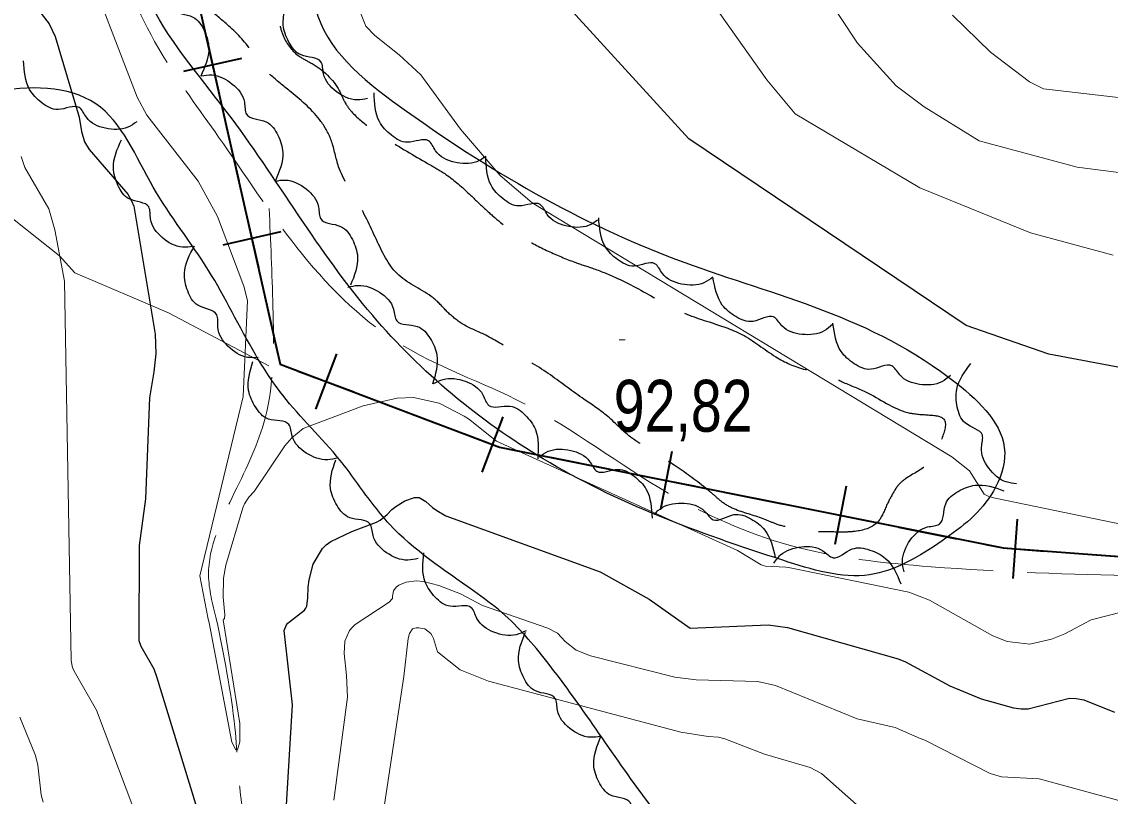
# Model space of a CAD drawing. Extents: x 483843 to 488449, y 4381269 to 4384483.
# Drawn here: x 486032.4 to 486216, y 4382919.1 to 4383049.8 of the extents above; entities that cross this region are included whole.
import ezdxf

# ---------------------------------------------------------------- set-up
doc = ezdxf.new("R2010")
doc.units = 0
doc.header["$LTSCALE"] = 3.8
doc.linetypes.add('LONG_DASHED', pattern=[7.5, 6, -1.5])
for name, color, linetype, lineweight in [('15', 7, 'LONG_DASHED', 13), ('25', 7, 'LONG_DASHED', 25), ('27', 7, 'Continuous', 25), ('34', 7, 'Continuous', 35), ('51', 7, 'Continuous', 13), ('7', 7, 'Continuous', 13), ('8', 7, 'Continuous', 25), ('9', 7, 'Continuous', 13)]:
    doc.layers.add(name, color=color, linetype=linetype, lineweight=lineweight)

msp = doc.modelspace()

# ---------------------------------------------------------------- linework, layer by layer
at = {"layer": '15'}
for points in [[(485400.79, 4383245.56), (485406.29, 4383244.41), (485437.45, 4383238.77), (485468.96, 4383231.4), (485504.33, 4383230.87), (485548.91, 4383220.24), (485591.04, 4383211.58), (485622.86, 4383204.36), (485651.32, 4383198.17), (485680.8, 4383195.25), (485706.08, 4383191.57), (485722.37, 4383193.95), (485735.23, 4383201.55), (485745.53, 4383213.76), (485759.02, 4383234.02), (485775.19, 4383262.78), (485795.18, 4383296.65), (485816.27, 4383323.61), (485841.16, 4383349.54), (485867.84, 4383369.45), (485913.47, 4383388.85), (485935.22, 4383394.97), (485958.89, 4383388.99), (485973.47, 4383381.81), (485979.32, 4383377.07), (485984.47, 4383370.85), (485987.04, 4383362.27), (485987.36, 4383354.02), (485987.36, 4383343.75), (485982.84, 4383337.15), (485969.6, 4383328.73), (485958.55, 4383321.85), (485945.63, 4383309.53), (485931.32, 4383300.15), (485906.76, 4383286.36), (485891.85, 4383276.39), (485880.57, 4383264.12), (485871.36, 4383244.47), (485865.12, 4383222.84), (485860.75, 4383191.43), (485865.12, 4383163.11), (485877.56, 4383143.14), (485893.96, 4383132.18), (485911.26, 4383131.69), (485923.31, 4383135.71), (485933.99, 4383143.04), (485949.29, 4383153.83), (485962.9, 4383167.19), (485985.6, 4383171.87), (486005.81, 4383170.22), (486029.34, 4383160.05), (486043.95, 4383149.41), (486042.89, 4383138.86), (486041.88, 4383131.75), (486041.4, 4383119.4), (486046.63, 4383078.7), (486048.42, 4383062.79), (486056.08, 4383044.24), (486065.61, 4383030.31), (486078.82, 4383011.67), (486095.82, 4382995.68), (486117.1, 4382985.39), (486141.45, 4382970.26), (486161.85, 4382961.49), (486185.85, 4382957.83), (486221.05, 4382956.33), (486256.43, 4382956.62), (486292.45, 4382960.13), (486324.15, 4382965.13)], [(486074.14, 4383018.28), (486074.78, 4383001.69), (486073.45, 4382982.9), (486068.31, 4382970.39), (486063.91, 4382956.44), (486065.22, 4382949.08)], [(486065.22, 4382949.08), (486068.35, 4382930.7), (486069.57, 4382917.3), (486071.08, 4382908.17), (486071.58, 4382901.05), (486070.87, 4382894.66), (486068.25, 4382890.26), (486062.57, 4382880.56), (486059.04, 4382876.29), (486052.85, 4382870.03), (486046.08, 4382862.7), (486043.37, 4382858.83), (486038.17, 4382851.61), (486033.87, 4382844.85), (486028.35, 4382834.48), (486026.38, 4382826.86), (486024.21, 4382822.55), (486017.26, 4382812.6), (486008.1, 4382800.28), (485993.48, 4382782.38), (485975.18, 4382760.9), (485963.64, 4382747.64), (485957.75, 4382737.18), (485954.51, 4382729.62), (485952.12, 4382724.77), (485950.95, 4382722.8), (485947.3, 4382716.88), (485942.92, 4382710.35), (485938.93, 4382702.4), (485932.72, 4382688.86), (485930.2, 4382678.69), (485929.47, 4382673.2), (485929.22, 4382666.52), (485929.23, 4382661.56), (485945.62, 4382617.44), (485946.62, 4382612.05), (485946.07, 4382605.06), (485939.39, 4382592.57), (485935.24, 4382580.86), (485934.32, 4382573.72), (485932.79, 4382562.81), (485931.33, 4382552.28), (485929.61, 4382543.47), (485925.71, 4382534.7), (485922.35, 4382529.61), (485920.15, 4382522.44), (485919, 4382506.82), (485919.09, 4382501.71), (485919.55, 4382484.39), (485919.25, 4382472.08), (485919.24, 4382464.2), (485918.57, 4382446.78), (485919.45, 4382426.99), (485920.81, 4382413.51), (485921.23, 4382407.06), (485920.41, 4382402.4), (485918.93, 4382396.89), (485917.32, 4382390.64), (485916.53, 4382388.45), (485911.11, 4382376.87), (485903.16, 4382363.9), (485897.69, 4382359.6), (485889.85, 4382348.8), (485888.47, 4382342.25), (485885.05, 4382333.08)]]:
    msp.add_spline(points, degree=3, dxfattribs=at)
at = {"layer": '25'}
for points in [[(486047.77, 4383119.06), (486047.87, 4383123.7), (486050.32, 4383126.96), (486057.32, 4383128.74), (486055.98, 4383129.28), (486056.91, 4383131.52), (486059.09, 4383131.79), (486063.4, 4383123.4), (486063.36, 4383120.85), (486067.05, 4383111.49), (486070.05, 4383106.12), (486072.24, 4383101.66), (486074.34, 4383096.76), (486075.26, 4383092.47), (486076.22, 4383085.92), (486076.34, 4383084.05), (486076.23, 4383081.87), (486076.15, 4383076.02), (486076.05, 4383074.14), (486075.99, 4383070.32), (486075.86, 4383066.04), (486075.99, 4383065.14), (486076.95, 4383064), (486078.58, 4383062.48), (486078.87, 4383061.87), (486077.97, 4383061.74), (486077.14, 4383061.75), (486076.99, 4383061.68), (486076.46, 4383061.31), (486075.61, 4383059.22), (486075.27, 4383056.67), (486075.13, 4383052.1), (486075.77, 4383049.69), (486076.56, 4383047.27), (486079.22, 4383043.93), (486081.37, 4383042.7), (486085.96, 4383038.14), (486087.05, 4383035.94), (486087.86, 4383034.81), (486090.98, 4383031.99), (486094.32, 4383029.76), (486101.31, 4383025.61), (486104.29, 4383023.77), (486108.14, 4383020.48), (486110.81, 4383017.97), (486113.18, 4383015.91), (486116.82, 4383013.38), (486121.22, 4383011.07), (486125.69, 4383009.2), (486128.9, 4383008.11), (486132.93, 4383006.47), (486139.86, 4383002.77), (486141.79, 4383001.69), (486148.36, 4382999.12), (486153.88, 4382997.02), (486159.6, 4382993.26), (486164.6, 4382991.09), (486168.12, 4382990.29), (486170.8, 4382989.05), (486174.75, 4382987.34), (486181.83, 4382983.86), (486185.35, 4382983.44), (486187.97, 4382982.72), (486187.62, 4382979.43), (486185.16, 4382975.03), (486181.52, 4382972.69), (486180.15, 4382971.43), (486179.61, 4382970.61), (486178.3, 4382968.15), (486176.69, 4382965.25), (486172.99, 4382963.8), (486171.04, 4382963.68), (486167.29, 4382963.74), (486165.78, 4382963.76), (486162.57, 4382964.33), (486159.87, 4382964.97), (486157.79, 4382965.82), (486152.86, 4382967.47), (486150.62, 4382968.7), (486149.36, 4382969.77), (486147.73, 4382971.14), (486142.46, 4382974.97), (486138, 4382977.81), (486135.1, 4382979.73), (486131.02, 4382983.39), (486126.94, 4382986.3), (486121.22, 4382990.43), (486115.12, 4382994.27), (486110.36, 4382997.04), (486106.71, 4382998.82), (486104.11, 4383000.88)], [(486104.11, 4383000.88), (486101.82, 4383003.17), (486096.02, 4383007), (486092.42, 4383012.61), (486089.07, 4383019.33), (486085.85, 4383025.31), (486084.64, 4383029.68), (486082.88, 4383032.93), (486077.85, 4383037.88), (486074.52, 4383040.63), (486072.52, 4383042.61), (486071.12, 4383044.8), (486067.06, 4383049.29), (486064.02, 4383051.88), (486062.17, 4383053.56), (486060.09, 4383055.09), (486057.86, 4383056.47), (486057.5, 4383057.53), (486056.29, 4383062.05), (486055.07, 4383076.17), (486053.75, 4383083.54), (486049.3, 4383087.21), (486048.84, 4383092.32), (486048.95, 4383099.6), (486048.96, 4383105.97), (486048.61, 4383112.96), (486045.38, 4383117.3)]]:
    msp.add_spline(points, degree=3, dxfattribs=at)
at = {"layer": '27'}
for points in [[(486069.89, 4383117.75), (486082.64, 4383091.41), (486082.37, 4383068.06), (486082.37, 4383050.69), (486097.3, 4383034.67), (486144.24, 4383009.15), (486190.1, 4382988.79), (486198.24, 4382977.12), (486196.34, 4382970.6), (486187.66, 4382962.19), (486175.45, 4382956.48), (486160.79, 4382958.93), (486120.36, 4382976.03), (486091.6, 4383000.19), (486066.9, 4383034.67), (486053.61, 4383053.95), (486049.81, 4383066.98), (486048.18, 4383082.45), (486040.85, 4383115.3), (486038.68, 4383122.9), (486038.68, 4383126.16), (486042.21, 4383132.14), (486051.17, 4383136.21), (486059.31, 4383137.29), (486063.38, 4383135.12), (486064.73, 4383132.95), (486069.89, 4383118.02)], [(486050.49, 4383058.59), (486052.26, 4383058.7), (486055.69, 4383057.07), (486057.66, 4383053.95), (486057.98, 4383051.92), (486061.26, 4383050.56), (486063.17, 4383048.27), (486063.95, 4383045.35), (486062.59, 4383040.57)], [(486090.74, 4383036.79), (486088.98, 4383036.58), (486085.46, 4383038), (486083.31, 4383041), (486082.87, 4383043), (486079.51, 4383044.16), (486077.47, 4383046.34), (486076.51, 4383049.21), (486077.59, 4383054.05)], [(486051.8, 4383032.89), (486050.29, 4383031.97), (486046.5, 4383031.8), (486043.3, 4383033.65), (486042.07, 4383035.29), (486038.53, 4383034.96), (486035.77, 4383036.1), (486033.72, 4383038.32), (486032.69, 4383043.17)], [(486062.68, 4383040.65), (486064.44, 4383040.79), (486067.91, 4383039.25), (486069.95, 4383036.18), (486070.31, 4383034.15), (486073.63, 4383032.87), (486075.59, 4383030.62), (486076.44, 4383027.72), (486075.19, 4383022.92)], [(486286.37, 4382818.73), (486278.04, 4382823.01), (486270.91, 4382827.39), (486261.25, 4382830.52), (486249.55, 4382838.56), (486235.78, 4382853.4), (486208.71, 4382873.4), (486199.54, 4382878.26), (486190.05, 4382880.8), (486172.3, 4382887.23), (486138.6, 4382917.4), (486120.98, 4382941.85), (486113.4, 4382950.11), (486108.61, 4382953.78), (486094.45, 4382965.01), (486088.77, 4382972.26), (486086.08, 4382975.81), (486076.44, 4382986.75), (486071.81, 4382993.64), (486063.9, 4383007.83), (486054.58, 4383021.85), (486044.87, 4383035.93), (486027.43, 4383037.8), (485933.61, 4382938.44), (485919.77, 4382940.14), (485889.7, 4382939.08), (485839.54, 4382941.26), (485816.75, 4382944.76), (485741.23, 4382929.61), (485713.92, 4382937.9), (485681.19, 4382964.56), (485670.78, 4382975.78), (485652.13, 4382986.85), (485638.34, 4382985.71), (485603.43, 4382978.48), (485583.93, 4382969.73), (485574.59, 4382959.14), (485576.9, 4382938.62), (485580.71, 4382884.66), (485577.11, 4382863.44), (485511.92, 4382842.02), (485496.71, 4382848.88), (485482.18, 4382864.38), (485474.15, 4382877.06), (485456.13, 4382915.83), (485453.46, 4382926.82), (485449.3, 4382945.73), (485443.9, 4382957.94), (485427.92, 4382978.81), (485418.61, 4382987.72), (485404.26, 4383001.65), (485381.54, 4383009.27), (485374.73, 4383011.94)], [(486110.69, 4383027.03), (486109.15, 4383026.15), (486105.36, 4383026.08), (486102.21, 4383028), (486101.02, 4383029.68), (486097.48, 4383029.43), (486094.75, 4383030.65), (486092.75, 4383032.91), (486091.85, 4383037.79)], [(486061.29, 4383011.84), (486059.52, 4383011.73), (486056.09, 4383013.36), (486054.13, 4383016.49), (486053.82, 4383018.52), (486050.53, 4383019.88), (486048.63, 4383022.18), (486047.85, 4383025.1), (486049.22, 4383029.87)], [(486129.53, 4383016.28), (486127.99, 4383015.4), (486124.2, 4383015.33), (486121.05, 4383017.26), (486119.86, 4383018.93), (486116.32, 4383018.69), (486113.59, 4383019.9), (486111.59, 4383022.17), (486110.69, 4383027.05)], [(486075.13, 4383022.88), (486076.89, 4383023.06), (486080.38, 4383021.56), (486082.46, 4383018.51), (486082.85, 4383016.49), (486086.18, 4383015.25), (486088.17, 4383013.02), (486089.05, 4383010.13), (486087.87, 4383005.32)], [(486149, 4383006.69), (486147.5, 4383005.74), (486143.71, 4383005.52), (486140.48, 4383007.31), (486139.23, 4383008.94), (486135.7, 4383008.55), (486132.92, 4383009.65), (486130.83, 4383011.83), (486129.73, 4383016.67)], [(486072.26, 4382993.12), (486070.49, 4382993.15), (486067.19, 4382995.02), (486065.46, 4382998.28), (486065.3, 4383000.33), (486062.12, 4383001.93), (486060.39, 4383004.36), (486059.83, 4383007.34), (486061.55, 4383011.99)], [(486169.19, 4382998.72), (486167.79, 4382997.63), (486164.05, 4382997.02), (486160.65, 4382998.47), (486159.24, 4382999.96), (486155.77, 4382999.21), (486152.89, 4383000.02), (486150.59, 4383001.98), (486149, 4383006.67)], [(486087.42, 4383004.97), (486089.16, 4383005.3), (486092.77, 4383004.13), (486095.11, 4383001.28), (486095.68, 4382999.3), (486099.12, 4382998.37), (486101.3, 4382996.34), (486102.44, 4382993.54), (486101.7, 4382988.64)], [(486189.08, 4382990.07), (486187.63, 4382989.04), (486183.87, 4382988.59), (486180.54, 4382990.19), (486179.19, 4382991.74), (486175.69, 4382991.14), (486172.85, 4382992.08), (486170.64, 4382994.13), (486169.25, 4382998.9)], [(486085.75, 4382976.2), (486084.01, 4382975.86), (486080.4, 4382977.02), (486078.04, 4382979.86), (486077.46, 4382981.83), (486074.02, 4382982.75), (486071.83, 4382984.78), (486070.67, 4382987.57), (486071.4, 4382992.48)], [(486200.25, 4382971.84), (486198.5, 4382972.13), (486195.53, 4382974.49), (486194.32, 4382977.98), (486194.47, 4382980.03), (486191.58, 4382982.09), (486190.24, 4382984.76), (486190.14, 4382987.78), (486192.54, 4382992.12)], [(486101.86, 4382988.73), (486103.49, 4382989.44), (486107.27, 4382989.11), (486110.19, 4382986.85), (486111.19, 4382985.06), (486114.74, 4382984.92), (486117.33, 4382983.43), (486119.07, 4382980.96), (486119.44, 4382976.01)], [(486119.69, 4382976.39), (486121.22, 4382977.31), (486125.01, 4382977.45), (486128.2, 4382975.6), (486129.42, 4382973.94), (486132.96, 4382974.26), (486135.71, 4382973.11), (486137.75, 4382970.88), (486138.76, 4382966.02)], [(486099.27, 4382959.24), (486097.52, 4382958.95), (486093.94, 4382960.21), (486091.66, 4382963.11), (486091.13, 4382965.09), (486087.72, 4382966.1), (486085.59, 4382968.18), (486084.5, 4382971.01), (486085.36, 4382975.89)], [(486181.25, 4382956.99), (486180.99, 4382958.75), (486182.3, 4382962.31), (486185.23, 4382964.55), (486187.22, 4382965.04), (486188.28, 4382968.44), (486190.4, 4382970.54), (486193.24, 4382971.58), (486198.11, 4382970.66)], [(486139.08, 4382966.69), (486140.44, 4382967.82), (486144.16, 4382968.55), (486147.6, 4382967.21), (486149.06, 4382965.76), (486152.51, 4382966.62), (486155.41, 4382965.91), (486157.77, 4382964.02), (486159.51, 4382959.38)], [(486117.48, 4382947.04), (486115.83, 4382946.37), (486112.06, 4382946.8), (486109.19, 4382949.12), (486108.24, 4382950.93), (486104.69, 4382951.16), (486102.14, 4382952.72), (486100.46, 4382955.23), (486100.21, 4382960.18)], [(486159.28, 4382958.45), (486160.42, 4382959.82), (486163.94, 4382961.21), (486167.57, 4382960.52), (486169.27, 4382959.36), (486172.5, 4382960.83), (486175.48, 4382960.66), (486178.15, 4382959.23), (486180.71, 4382954.98)], [(486130.11, 4382929.24), (486128.34, 4382929.07), (486124.86, 4382930.57), (486122.79, 4382933.63), (486122.4, 4382935.64), (486119.07, 4382936.88), (486117.08, 4382939.11), (486116.2, 4382942.01), (486117.39, 4382946.82)], [(486142.76, 4382911.6), (486140.99, 4382911.44), (486137.51, 4382912.96), (486135.45, 4382916.02), (486135.08, 4382918.04), (486131.75, 4382919.3), (486129.77, 4382921.54), (486128.9, 4382924.43), (486130.12, 4382929.24)]]:
    msp.add_spline(points, degree=3, dxfattribs=at)
at = {"layer": '34'}
for p, q in [((486063.48, 4383047.32), (486065.69, 4383037.57)), ((486069.46, 4383043.55), (486059.71, 4383041.34)), ((486066.79, 4383032.69), (486069, 4383022.94)), ((486070.1, 4383018.07), (486072.31, 4383008.32)), ((486076.08, 4383014.3), (486066.33, 4383012.09)), ((486073.41, 4383003.44), (486075.62, 4382993.69)), ((486085.49, 4382993.75), (486081.95, 4382984.4)), ((486079.05, 4382990.85), (486088.4, 4382987.31)), ((486093.08, 4382985.54), (486102.43, 4382982)), ((486113.54, 4382983.14), (486110, 4382973.79)), ((486121.52, 4382976.3), (486131.32, 4382974.34)), ((486142.1, 4382977.28), (486140.14, 4382967.47)), ((486136.22, 4382973.36), (486146.02, 4382971.4)), ((486171.51, 4382971.4), (486169.55, 4382961.59)), ((486150.93, 4382970.41), (486160.73, 4382968.45)), ((486165.63, 4382967.47), (486175.43, 4382965.51)), ((486200.34, 4382965.84), (486199.6, 4382955.87)), ((486180.33, 4382964.53), (486190.14, 4382962.57)), ((486209.94, 4382960.12), (486219.91, 4382959.38))]:
    msp.add_line(p, q, dxfattribs=at)
for points in [[(485677, 4383181), (485719, 4383181), (485742, 4383197), (485784, 4383269), (485864, 4383366), (485911, 4383378), (485964, 4383376), (485987, 4383356), (485989, 4383335), (485950, 4383293), (485897, 4383256), (485871, 4383214), (485861, 4383180), (485872, 4383150), (485894, 4383132), (485920, 4383135), (485958, 4383157), (485987, 4383165), (486023, 4383161), (486045, 4383129), (486076, 4382992), (486113, 4382978), (486198, 4382961), (486252, 4382957)], [(486107.1, 4382980.23), (486113, 4382978), (486116.62, 4382977.28)], [(486195.03, 4382961.59), (486198, 4382961), (486204.96, 4382960.48)]]:
    msp.add_lwpolyline(points, dxfattribs=at)
at = {"layer": '51'}
msp.add_lwpolyline([(485984.11, 4383046.35), (486000.43, 4383038.91), (486015.23, 4383029.77), (486023.48, 4383023.73), (486031.1, 4383016.34), (486038.74, 4383010.3), (486041.33, 4383007.41), (486057.14, 4383000.66), (486074.09, 4382991.74)], dxfattribs=at)
at = {"layer": '7'}
msp.add_line((486133.18, 4382996.11), (486134.18, 4382996.11), dxfattribs=at)
at = {"layer": '8'}
for points in [[(486031.5, 4383056.58), (486032.91, 4383054.13), (486033.73, 4383053.06), (486035.3, 4383051.63), (486037.01, 4383049.42), (486038.01, 4383047.25), (486042.1, 4383033.66), (486042.46, 4383031.22), (486043, 4383029.48), (486043.79, 4383028.22), (486050.3, 4383020.66), (486050.91, 4383019.56), (486051.29, 4383018.63), (486054.88, 4382997.08), (486055.03, 4382993.76), (486054.68, 4382990.7), (486053.94, 4382986.31), (486053.29, 4382969.3), (486052.2, 4382961.4), (486052.13, 4382945.42), (486052.5, 4382944.42), (486054.68, 4382940.62), (486055.11, 4382939.35), (486064.46, 4382908.84)], [(486250.77, 4382985.2), (486205.67, 4382993.71), (486191.73, 4382998.54), (486144.97, 4383030.01), (486120.47, 4383056.81)], [(486075.73, 4382895.13), (486078.09, 4382934.55), (486076.65, 4382947.06), (486077.07, 4382948.04), (486077.28, 4382948.3), (486077.55, 4382948.57), (486080.11, 4382950.52), (486080.33, 4382950.85), (486080.5, 4382951.19), (486080.67, 4382952.61), (486080.69, 4382954.41), (486080.89, 4382955.64), (486081.58, 4382958.28), (486083.12, 4382960.89), (486083.77, 4382961.51), (486084.53, 4382962.08), (486088.07, 4382963.77), (486092.25, 4382965.38), (486092.84, 4382965.68), (486094.07, 4382966.62), (486094.84, 4382967.48), (486095.48, 4382967.98), (486097.03, 4382968.93), (486098.67, 4382969.51), (486099.07, 4382969.54), (486099.44, 4382969.49), (486100.59, 4382968.84), (486101.7, 4382967.83), (486102.42, 4382967.31), (486103.93, 4382966.43), (486130, 4382956.98), (486138.25, 4382952.38), (486145.18, 4382947.45), (486158.35, 4382948.03), (486161.58, 4382947.6), (486180.28, 4382942.3), (486181.52, 4382941.79), (486188.97, 4382937.74), (486194.29, 4382935.56), (486199.74, 4382934.02), (486201.03, 4382933.88), (486202.22, 4382933.86), (486209.17, 4382935.69), (486210.32, 4382935.59), (486211.56, 4382935.36), (486216.76, 4382933.32)]]:
    msp.add_lwpolyline(points, dxfattribs=at)
at = {"layer": '9'}
for points in [[(486324.1, 4383010.67), (486210.45, 4383025.25), (486193.91, 4383029.68), (486184.64, 4383035.41), (486179.94, 4383038.96), (486173.4, 4383046.15), (486154.02, 4383075.48)], [(486106.44, 4383031.66), (486099.73, 4383040.81), (486096.08, 4383044.2), (486091.94, 4383047.46), (486090.45, 4383049.02), (486085.66, 4383061.12)], [(486145.4, 4383057.94), (486158.13, 4383039.94), (486162.87, 4383034.25), (486183.91, 4383021.75), (486202.56, 4383014.17), (486216.54, 4383010.41)], [(486046.26, 4383051.63), (486051.84, 4383037.04), (486053.5, 4383034), (486062.14, 4383022.87), (486065.42, 4383016.93), (486069.87, 4383005.14), (486070.49, 4383002.74), (486069.74, 4382986.55), (486062.41, 4382956.31), (486063.84, 4382949.02), (486064.04, 4382948.39), (486067.86, 4382928.22), (486068.52, 4382926.94), (486068.67, 4382926.88), (486068.81, 4382926.95), (486069.2, 4382928.28), (486069.2, 4382931.38), (486066.39, 4382948.87), (486066.43, 4382948.97), (486066.45, 4382949), (486066.48, 4382949.02), (486066.61, 4382949.12), (486066.68, 4382949.73), (486066.4, 4382952.72), (486066.45, 4382955.92), (486066.8, 4382958.1), (486069.71, 4382967.77), (486069.98, 4382968.44), (486070.7, 4382969.58), (486071.59, 4382970.5), (486076.8, 4382978.23), (486077.96, 4382979.59), (486079.85, 4382981.13), (486089.98, 4382984.97), (486095.71, 4382986.29), (486098.5, 4382986.38), (486102.83, 4382985.4), (486107.03, 4382983.22), (486107.75, 4382982.76), (486112.49, 4382979.02), (486153.18, 4382960.56), (486157.12, 4382958.18), (486157.49, 4382958.03), (486157.87, 4382957.92), (486161.33, 4382957.79), (486161.77, 4382957.72), (486182.04, 4382953.54), (486185.57, 4382952.22), (486196.21, 4382946.18), (486198.63, 4382945.25), (486202.45, 4382944.8), (486206.15, 4382945.63), (486208.4, 4382946.52), (486212.83, 4382948.9), (486218.36, 4382950.3)], [(486352.44, 4383021.34), (486204.78, 4383038.42), (486202.43, 4383039.61), (486195.82, 4383044.65), (486189.4, 4383050.86)], [(486229.79, 4382962.53), (486196.61, 4382969.38), (486195.58, 4382969.71), (486194.79, 4382970.06), (486192.3, 4382974.03), (486189.3, 4382976.35), (486118.52, 4383019.19), (486113.13, 4383023.85), (486106.44, 4383031.66)], [(486052.58, 4382913.51), (486045.03, 4382933.65), (486041.45, 4382939.82), (486040.97, 4382940.81), (486040.71, 4382942.05), (486039.61, 4383006.01), (486037.99, 4383014.66), (486036.94, 4383018.18), (486032.9, 4383025.15), (486032.28, 4383027.02)], [(486233.39, 4382914.09), (486204.04, 4382922.07), (486197.69, 4382922.39), (486195.81, 4382922.98), (486184.75, 4382928.6), (486183.95, 4382928.84), (486179.73, 4382930.71), (486173.33, 4382932.2), (486159.58, 4382937.81), (486156.56, 4382938.5), (486146.16, 4382938.76), (486142.57, 4382939.22), (486128.33, 4382942.81), (486125.96, 4382943.76), (486124.1, 4382945.25), (486122.78, 4382946.64), (486121.17, 4382947.47), (486110.11, 4382951.3), (486106.41, 4382953.27), (486102.74, 4382954.68), (486100.17, 4382955.32), (486098.98, 4382955.44), (486097.25, 4382955.23), (486096.04, 4382954.71), (486095.79, 4382954.55), (486095.58, 4382954.39), (486095.13, 4382953.77), (486094.98, 4382953.18), (486094.93, 4382952.9), (486094.93, 4382952.5), (486094.37, 4382951.88), (486088.62, 4382948.11), (486088.12, 4382947.61), (486087.71, 4382947.11), (486086.92, 4382945.26), (486086.81, 4382943.23), (486087.21, 4382939.51), (486087.33, 4382935.82), (486085.02, 4382918.46)], [(486088.64, 4382884.94), (486096.83, 4382939.32), (486097.57, 4382945.74), (486097.82, 4382946.6), (486098.32, 4382947.38), (486098.95, 4382947.56), (486099.4, 4382947.55), (486100.39, 4382947.34), (486101.39, 4382946.55), (486101.63, 4382946.16), (486101.86, 4382945.71), (486102.56, 4382943.47), (486106.34, 4382940.45), (486111.14, 4382938.51), (486143.61, 4382929.92), (486148.19, 4382929.2), (486149.94, 4382929.1), (486151.03, 4382928.83), (486157.71, 4382926.25), (486165.42, 4382923.98), (486167.31, 4382922.95), (486174.23, 4382916.86)], [(486032.09, 4382932.45), (486034.7, 4382926.01), (486035.1, 4382924.37), (486035.64, 4382919.36), (486036.02, 4382918.13)]]:
    msp.add_lwpolyline(points, dxfattribs=at)

# ---------------------------------------------------------------- texts
at = {"layer": '7', "width": 0.8}
msp.add_text('92,82', height=8.75, dxfattribs=at).set_placement((486132.27, 4382980.61))

doc.saveas('drawing.dxf')
